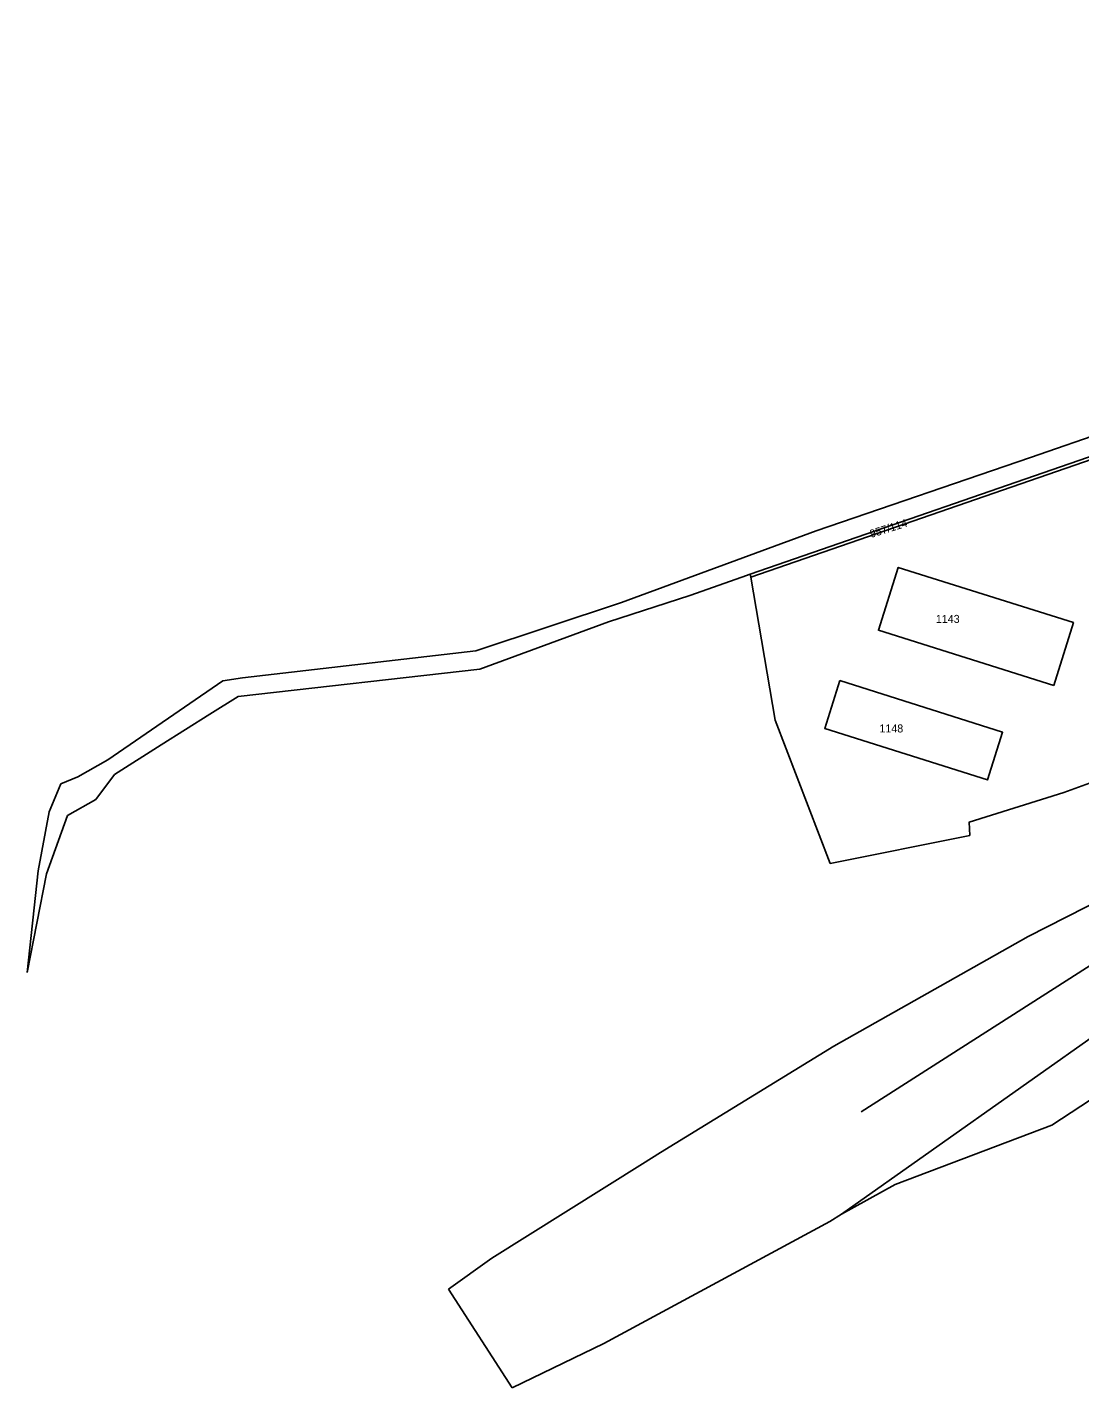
# Model space of a CAD drawing. Extents: x -752184 to -751416, y -1028299 to -1027836.
# Drawn here: x -752184.2 to -751921.2, y -1028298.9 to -1027958.9 of the extents above; entities that cross this region are included whole.
import ezdxf

# ---------------------------------------------------------------- set-up
doc = ezdxf.new("R2010")
doc.units = 0
for name, color, linetype in [('Vrstva 53', 7, 'Continuous'), ('Vrstva 55', 7, 'Continuous'), ('Vrstva 57', 7, 'Continuous'), ('Vrstva 63', 7, 'Continuous')]:
    doc.layers.add(name, color=color, linetype=linetype)

msp = doc.modelspace()

# ---------------------------------------------------------------- linework, layer by layer
at = {"layer": 'Vrstva 53'}
for points in [[(-752078.91, -1028274.27), (-752068.08, -1028266.53), (-752030.45, -1028242.94), (-752025.93, -1028240.15), (-751982.6, -1028213.59), (-751934.1, -1028186.19), (-751914.9, -1028176.41)], [(-751864.36, -1028191.47), (-751928.16, -1028233.3), (-751967.27, -1028248.1), (-751980.73, -1028255.56), (-751983.66, -1028257.34), (-752040.12, -1028287.87), (-752063.02, -1028298.92)]]:
    msp.add_lwpolyline(points, dxfattribs=at)
at = {"layer": 'Vrstva 55'}
for p, q in [((-751881.38, -1028054.14), (-752003.38, -1028096.4)), ((-751913.74, -1028059.67), (-751933.45, -1028066.43)), ((-752003.56, -1028095.62), (-752005.66, -1028096.36)), ((-752003.38, -1028096.4), (-752003.56, -1028095.62)), ((-752072.09, -1028114.77), (-752130.41, -1028121.51)), ((-752138.59, -1028130.64), (-752150.71, -1028138.27)), ((-752171.57, -1028146.24), (-752175.83, -1028148.04)), ((-751983.58, -1028167.93), (-751948.62, -1028160.91)), ((-751882.55, -1028186.22), (-751980.73, -1028255.56)), ((-752030.45, -1028242.94), (-752025.93, -1028240.15)), ((-751980.73, -1028255.56), (-751983.66, -1028257.34)), ((-752063.02, -1028298.92), (-752078.91, -1028274.27))]:
    msp.add_line(p, q, dxfattribs=at)
for points in [[(-752003.56, -1028095.62), (-751908.15, -1028062.63), (-751881.38, -1028054.14)], [(-752072.09, -1028114.77), (-752035.67, -1028102.67), (-751987.04, -1028084.81), (-751933.45, -1028066.43)], [(-751927.67, -1028123.47), (-751971.5, -1028109.63), (-751966.53, -1028093.91), (-751922.77, -1028107.71), (-751927.67, -1028123.47)], [(-752071.11, -1028119.33), (-752038.95, -1028107.53), (-752018.63, -1028100.96), (-752005.66, -1028096.36)], [(-751983.58, -1028167.93), (-751997.32, -1028132.13), (-752003.38, -1028096.4)], [(-752171.57, -1028146.24), (-752164.12, -1028142.01), (-752135.34, -1028122.25), (-752130.41, -1028121.51)], [(-752071.11, -1028119.33), (-752131.47, -1028126.16), (-752138.59, -1028130.64)], [(-751981.1, -1028122.22), (-751940.47, -1028135.13), (-751944.23, -1028147.01), (-751984.89, -1028134.14), (-751981.1, -1028122.22)], [(-752150.71, -1028138.27), (-752162.4, -1028145.64), (-752167.07, -1028151.94)], [(-752184.23, -1028195.14), (-752181.48, -1028169.72), (-752178.76, -1028155.03), (-752175.83, -1028148.04)], [(-751948.62, -1028160.91), (-751948.85, -1028157.62), (-751925.12, -1028150.18), (-751915.97, -1028146.83)], [(-752167.07, -1028151.94), (-752174.15, -1028155.95), (-752179.37, -1028170.52), (-752184.23, -1028195.14)], [(-751837.73, -1028166.78), (-751864.36, -1028191.47), (-751928.16, -1028233.3), (-751967.27, -1028248.1), (-751980.73, -1028255.56)], [(-752025.93, -1028240.15), (-751982.6, -1028213.59), (-751934.1, -1028186.19), (-751914.9, -1028176.41), (-751903.43, -1028170.23)], [(-752078.91, -1028274.27), (-752068.08, -1028266.53), (-752030.45, -1028242.94)], [(-751983.66, -1028257.34), (-752040.12, -1028287.87), (-752063.02, -1028298.92)]]:
    msp.add_lwpolyline(points, dxfattribs=at)
at = {"layer": 'Vrstva 63'}
msp.add_line((-751551.77, -1027958.95), (-751975.84, -1028230), dxfattribs=at)

# ---------------------------------------------------------------- texts
at = {"layer": 'Vrstva 57'}
msp.add_text('957/114', height=2, rotation=17.4652, dxfattribs=at).set_placement((-751973.3, -1028086.57))
for s, p in [('1143', (-751957.14, -1028107.8)), ('1148', (-751971.24, -1028135.17))]:
    msp.add_text(s, height=2, dxfattribs=at).set_placement(p)

doc.saveas('drawing.dxf')
